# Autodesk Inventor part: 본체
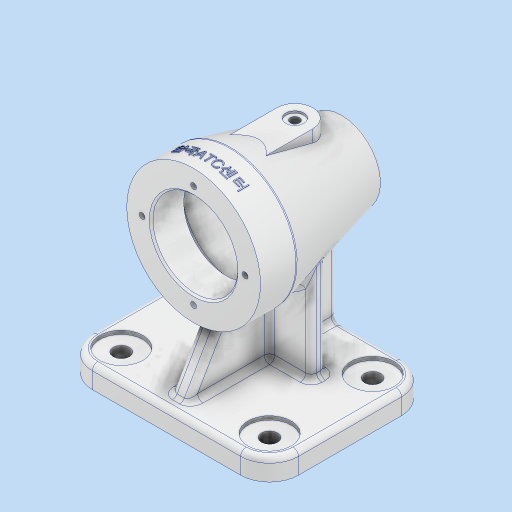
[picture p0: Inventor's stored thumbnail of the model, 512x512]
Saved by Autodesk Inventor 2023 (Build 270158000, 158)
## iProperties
Created: 2024-12
Part Number: 본체
Material: 알루미늄 6061
Document SubType Name: Modeling
Designer: asung
Density: 2.7 g/cm^3
Appearance: 알루미늄 - 평지
Mass: 746.172 g
Surface Area: 670.78 cm^2
Volume: 276.36 cm^3
Author: asung
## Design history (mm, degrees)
sketch "스케치1"
  geometry: L1 (-41, 44.5)-(41, 44.5); L2 (57, 28.5)-(57, -28.5); L3 (41, -44.5)-(-41, -44.5); L4 (-57, -28.5)-(-57, 28.5); L5 (-57, 44.5)-(57, -44.5); L6 (57, 44.5)-(-57, -44.5); C1 r 4.5 at (41, -28.5); C2 r 4.5 at (-41, -28.5); C3 r 4.5 at (-41, 28.5); C4 r 4.5 at (41, 28.5); A1 r 16 centre (41, -28.5) between (41, -44.5) and (57, -28.5); A2 r 16 centre (-41, -28.5) between (-57, -28.5) and (-41, -44.5); A3 r 16 centre (41, 28.5) between (57, 28.5) and (41, 44.5); A4 r 16 centre (-41, 28.5) between (-41, 44.5) and (-57, 28.5); 2 further points
  constraints: 12 end point, 8 centre point, 8 point on circle, 8 point on line, 8 tangent, 4 coincident, 3 equal radius, 3 midpoint, 2 parallel, 1 horizontal, 1 perpendicular
  dimensions: "d0" = 114 distance of L5.end L6.end; "d1" = 89 distance from line of point (0, 44.5) L3; "d2" = 16 radius of A1; "d3" = 4.5 radius of C1; "d4" = 4.5 radius of C2; "d6" = 4.5 radius of C3; "d7" = 4.5 radius of C4
extrude "돌출1" new body sketch "스케치1" distance "d8" = 12; taper "d9" = 0 deg
sketch "스케치2"
  geometry: A1 r 16 centre (-41, 28.5) between (-41, 44.5) and (-57, 28.5) reference; A2 r 16 centre (41, 28.5) between (57, 28.5) and (41, 44.5) reference; A3 r 16 centre (-41, -28.5) between (-57, -28.5) and (-41, -44.5) reference; A4 r 16 centre (41, -28.5) between (41, -44.5) and (57, -28.5) reference; 5 further points
  constraints: 4 coincident
hole "구멍1" sketch "스케치2" at (-41, 28.5), (41, 28.5), (-41, -28.5), (41, -28.5) diameter "d10" = 9; stored, may be unused: countersink angle "d14" = 90 deg, drill point angle "d16" = 0 deg; dims "d11" = 6, "d12" = 24, "d13" = 2, "d15" = 12
sketch "스케치3"
  geometry: L1 (12, -44.5)-(0, -44.5) reference; L2 (0, -44.5)-(0, 44.5) reference; L3 (0, 44.5)-(12, 44.5) reference; L4 (12, 44.5)-(12, -44.5) reference; L5 (82, -85.109)-(82, 114.888); L6 (119, 29.5)-(119, 9.5); L7 (119, 9.5)-(103, -54.5); L8 (103, -54.5)-(82, -54.5); L9 (82, -46.5)-(94.5, -46.5); L10 (97.5, -43.5)-(97.5, -43.5); L11 (97.5, -43.5)-(99.5, -43.5); L12 (103.664, -31.228)-(112.793, 5.287); L13 (107.942, 11.5)-(105.5, 11.5); L14 (105.5, 11.5)-(105.5, 29.5); L15 (105.5, 29.5)-(119, 29.5); L16 (99.5, -43.5)-(99.5, -33.5); L17 (99.5, -33.5)-(100.754, -33.5); A1 r 5 centre (107.942, 6.5) between (112.793, 5.287) and (107.942, 11.5); A2 r 3 centre (94.5, -43.5) between (94.5, -46.5) and (97.5, -43.5); A3 r 3 centre (100.754, -30.5) between (100.754, -33.5) and (103.664, -31.228); 4 further points
  constraints: 26 end point, 6 point on circle, 6 tangent, 4 vertical, 3 centre point, 3 perpendicular, 3 point on line, 2 horizontal, 2 parallel
  dimensions: "d17" = 82 distance between parallel lines of L5 L2; "d18" = 84 vertical distance of L6.start L8.end; "d19" = 15 vertical distance of L3.end L6.start; "d22" = 74 diameter of L6 L5; "d23" = 20 distance of L6.start L6.end; "d25" = 42 diameter of L7.end L5; "d26" = 18 distance of L13.end L14.end; "d27" = 5 distance between parallel lines of L7 L12; "d28" = 47 diameter of L14 L5; "d29" = 5 radius of A1; "d32" = 45 vertical distance of L13.end point (103.096, -33.5); "d33" = 3 distance between parallel lines of L11 L9; "d34" = 35 diameter of L16 L5; "d35" = 31 diameter of L10 L5; "d36" = 3 radius of A2; "d37" = 10 distance of L11.end L16.end; "d38" = 13 distance from line of L9 point (103.096, -33.5); "d39" = 3 radius of A3
revolve "회전1" sketch "스케치3" stored, may be unused: angle "d40" = 90 deg
node "작업 평면1"
sketch "스케치4"
  geometry: L1 (10, -26.5)-(-10, -26.5); L2 (-10, -26.5)-(-10, -0.572); L3 (10, -0.572)-(10, -26.5); L4 (10, -26.5)-(-10, 2.036); L5 (-10, -26.5)-(10, 2.036); L6 (37, 29.5)-(-37, 29.5) reference; L7 (-16.733, 9.5)-(-16.733, 29.5) reference; L8 (-16.733, 29.5)-(16.733, 29.5) reference; L9 (16.733, 29.5)-(16.733, 9.5) reference; L10 (-16.733, 9.5)-(-16.733, 29.5) reference; L11 (-16.733, 29.5)-(16.733, 29.5) reference; L12 (16.733, 29.5)-(16.733, 9.5) reference; C1 r 10 at (0, -26.5); 6 further points
  constraints: 10 end point, 3 midpoint, 1 centre point, 1 horizontal, 1 parallel, 1 perpendicular, 1 tangent, 4 other
  dimensions: "d42" = 56 distance from line of L6 C1.centre; "d43" = 20 distance between parallel lines of L2 L3; "d44" = 10 distance from line of L2 point (0, 0)
extrude "돌출2" join sketch "스케치4" stored distance "d45" = 10; taper "d46" = 0 deg
chamfer "모따기1" distance "d47" = 1; stored, may be unused: second distance "d48" = 2, angle "d49" = 45 deg
fillet "모깎기1" dims "d50" = 0.3
sketch "스케치5"
  geometry: A1 r 10 centre (0, 26.5) between (10, 26.5) and (-10, 26.5) reference; 2 further points
  constraints: 1 coincident
hole "구멍2" sketch "스케치5" at (0, 26.5) diameter "d51" = 5.1881; stored, may be unused: countersink angle "d55" = 90 deg, drill point angle "d57" = 0 deg; dims "d52" = 12, "d53" = 10, "d54" = 1, "d56" = 16
sketch "스케치6"
  geometry: L1 (41, 44.5)-(-41, 44.5) reference; L2 (-5, 7.5)-(5, 7.5); L3 (5, 7.5)-(5, 44.5); L4 (5, 44.5)-(-5, 44.5); L5 (-5, 44.5)-(-5, 7.5); L6 (-5, 7.5)-(5, 44.5); L7 (5, 7.5)-(-5, 44.5); L8 (-28, 15.5)-(28, 15.5); L9 (28, 15.5)-(28, 7.5); L10 (28, 7.5)-(-28, 7.5); L11 (-28, 7.5)-(-28, 15.5); L12 (-28, 15.5)-(28, 7.5); L13 (28, 15.5)-(-28, 7.5); L14 (-41, -44.5)-(41, -44.5) reference; 8 further points
  constraints: 24 end point, 6 midpoint, 4 parallel, 2 horizontal, 2 perpendicular, 2 point on line
  dimensions: "d59" = 56 distance of L8.start L8.end; "d60" = 5 distance of point (-5, 26) point (0, 26); "d61" = 0 horizontal distance of point (0, 11.5) point (0, 26); "d98" = 29 distance between parallel lines of L1 L8; "d99" = 8 distance between parallel lines of L10 L8; "d100" = 28 distance from line of point (0, -44.5) L11
extrude "돌출3" join sketch "스케치6" stored distance "d63" = 10; taper "d64" = 0 deg
sketch "스케치7"
  geometry: L1 (12, 37.5)-(45, 18.447); L2 (57.5, 29.5)-(58.5, 28.5) reference; L3 (58.5, 28.5)-(58.5, 11.5) reference; L4 (58.5, 11.5)-(56.058, 11.5) reference; L5 (51.207, 5.287)-(60.336, -31.228) reference; L6 (63.246, -33.5)-(63.5, -33.5) reference; L7 (63.5, -33.5)-(64.5, -34.5) reference; L8 (64.5, -34.5)-(64.5, -43.2) reference; L9 (64.8, -43.5)-(66.5, -43.5) reference; L10 (69.5, -46.5)-(94.5, -46.5) reference; L11 (97.5, -43.5)-(99.2, -43.5) reference; L12 (99.5, -43.2)-(99.5, -34.5) reference; L13 (99.5, -34.5)-(100.5, -33.5) reference; L14 (100.5, -33.5)-(100.754, -33.5) reference; L15 (103.664, -31.228)-(104.198, -29.094) reference; L16 (104.198, -29.094)-(114, -29.094) reference; L17 (114, -29.094)-(114, -31.5) reference; L18 (114, -31.5)-(115, -31.5) reference; L19 (115, -31.5)-(115, -36.5) reference; L20 (115, -36.5)-(107.5, -36.5) reference; L21 (107.5, -36.5)-(103, -54.5) reference; L22 (61, -54.5)-(58.5, -44.5) reference; L23 (58.5, -44.5)-(0, -44.5) reference; L24 (0, -44.5)-(0, 44.5) reference; L25 (0, 44.5)-(12, 44.5) reference; L26 (12, 44.5)-(12, -7.5) reference; L27 (12, -7.5)-(49.25, -7.5) reference; L28 (49.25, -7.5)-(45, 9.5) reference; L29 (45, 9.5)-(45, 29.5) reference; L30 (45, 29.5)-(57.5, 29.5) reference; L31 (105.5, 28.5)-(106.5, 29.5) reference; L32 (106.5, 29.5)-(119, 29.5) reference; L33 (119, 29.5)-(119, 9.5) reference; L34 (119, 9.5)-(115, -6.5) reference; L35 (115, -6.5)-(115, -21.5) reference; L36 (115, -21.5)-(114, -21.5) reference; L37 (114, -21.5)-(114, -23.906) reference; L38 (114, -23.906)-(105.495, -23.906) reference; L39 (105.495, -23.906)-(112.793, 5.287) reference; L40 (107.942, 11.5)-(105.5, 11.5) reference; L41 (105.5, 11.5)-(105.5, 28.5) reference; L42 (103, -54.5)-(61, -54.5) reference; A1 r 5 centre (56.058, 6.5) between (56.058, 11.5) and (51.207, 5.287) reference; A2 r 3 centre (63.246, -30.5) between (60.336, -31.228) and (63.246, -33.5) reference; A3 r 0.3 centre (64.8, -43.2) between (64.5, -43.2) and (64.8, -43.5) reference; A4 r 3 centre (69.5, -43.5) between (66.5, -43.5) and (69.5, -46.5) reference; A5 r 3 centre (94.5, -43.5) between (94.5, -46.5) and (97.5, -43.5) reference; A6 r 0.3 centre (99.2, -43.2) between (99.2, -43.5) and (99.5, -43.2) reference; A7 r 3 centre (100.754, -30.5) between (100.754, -33.5) and (103.664, -31.228) reference; A8 r 5 centre (107.942, 6.5) between (112.793, 5.287) and (107.942, 11.5) reference; 1 further point
  constraints: 2 end point, 2 point on line
  dimensions: "d65" = 7 distance from line of L25 L1.start; "d66" = 60 deg angle of L26 L1
feature "리브1" sketch "스케치7" dims "d67" = 1, "d68" = 10, "d69" = 0, "d70" = 0, "d71" = 1, "d72" = 1
fillet "모깎기3" dims "d73" = 3
fillet "모깎기4" dims "d74" = 3
fillet "모깎기5" dims "d75" = 3
fillet "모깎기6" dims "d76" = 3
node "작업 평면3"
sketch "스케치8"
  geometry: L1 (37, 10)-(-37, 10) reference; L2 (41, 25)-(-41, 25) reference; L3 (21, -74)-(-21, -74) reference; L4 (37, -10)-(-37, -10) reference; 4 further points
  constraints: 1 vertical alignment, 1 other
  dimensions: "d77" = 9 distance from line of L1 point (0, 1); "d79" = 84 distance between parallel lines of L1 L3 (derived); "d80" = 20 distance between parallel lines of L1 L4 (derived); "d81" = 99 distance between parallel lines of L2 L3 (derived)
feature "엠보싱1" sketch "스케치8" dims "d0" = 114, "d1" = 89, "d2" = 16, "d3" = 4.5, "d4" = 4.5, "d6" = 4.5, "d7" = 4.5, "d82" = 0.5, "d83" = 0
fillet "모깎기7" dims "d84" = 3
sketch "스케치9" dims "d86" = 57
  geometry: C1 r 37 at (0, 0) reference; C2 r 24.5 at (0, 0) reference; 6 further points
  constraints: 2 vertical alignment, 1 coincident, 7 other
  dimensions: "d89" = 360 deg dimension on C1.centre point (0, 28.5) (derived)
hole "구멍3" sketch "스케치9" at (0, 28.5), (-28.5, 0), (0, -28.5), (28.5, 0) diameter "d91" = 3.242; stored, may be unused: countersink angle "d95" = 90 deg, drill point angle "d97" = 118 deg; dims "d92" = 8, "d93" = 10, "d94" = 1, "d96" = 10
feature "ͽ耀Ϳ耀΁耀΃耀΅耀·耀Ή耀΋耀" dims "d0" = 114, "d1" = 89, "d2" = 16, "d3" = 4.5, "d4" = 4.5, "d6" = 4.5, "d7" = 4.5, "d8" = 12, "d9" = 0, "d10" = 9, "d11" = 6, "d12" = 24, "d13" = 2, "d14" = 90 deg, "d15" = 12, "d16" = 0, "d17" = 82, "d18" = 84, "d19" = 15, "d22" = 74, "d23" = 20, "d25" = 42, "d26" = 18, "d27" = 5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
node "솔리드1"
node "절단 모서리 투영1"
node "절단 모서리 투영2"
node "절단 모서리 투영3"
node "절단 모서리 투영4"
feature "A9D066F2-1C7D-4E18-AEED-F7BC21143FA4" dims "d10" = 9, "d11" = 6, "d12" = 24, "d13" = 2, "d14" = 90 deg, "d15" = 12, "d16" = 0
